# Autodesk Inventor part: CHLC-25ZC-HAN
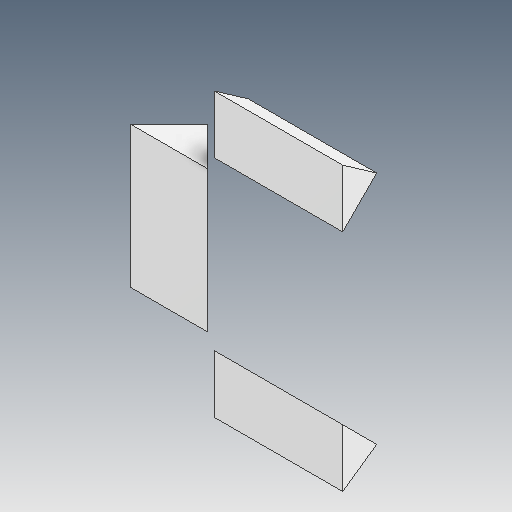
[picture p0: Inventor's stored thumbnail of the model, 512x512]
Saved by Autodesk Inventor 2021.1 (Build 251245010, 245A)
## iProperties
Created: 2021-05
Part Number: CHLC-25ZC-HAN
Material: Ogólny
Document SubType Name: Modeling
Designer: user
Density: 1 g/cm^3
Appearance: Domyślna
Author: user
Revision Number: ÈÎºÎ
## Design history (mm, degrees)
feature "ÊäÈë1"
feature "ÊäÈë2"
feature "ÊäÈë3"
node "Bryła1"
node "Bryła2"
node "Bryła3"
